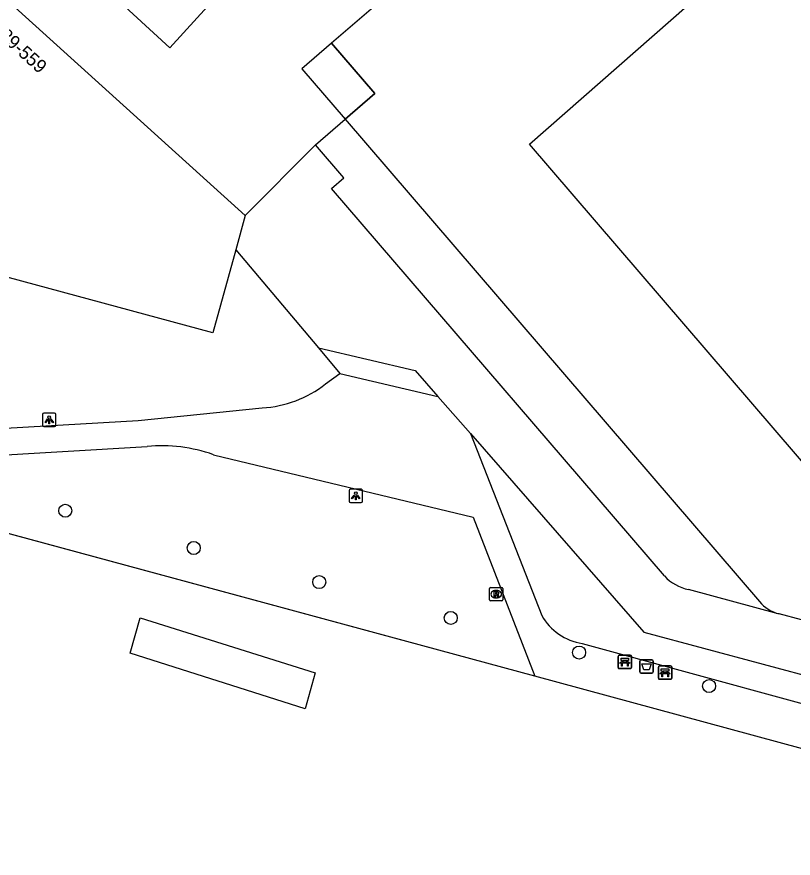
# Model space of a CAD drawing. Extents: x 161772 to 163123, y 383092 to 383917.
# Drawn here: x 162073.6 to 162131.9, y 383101.7 to 383164.9 of the extents above; entities that cross this region are included whole.
import ezdxf

# ---------------------------------------------------------------- set-up
doc = ezdxf.new("R2010")
doc.units = 0
for name, color, linetype in [('IMGEO_Afvalbak', 7, 'Continuous'), ('IMGEO_Bank', 7, 'Continuous'), ('IMGEO_Boom', 7, 'Continuous'), ('IMGEO_Kademuur', 7, 'Continuous'), ('IMGEO_Lichtpunt', 7, 'Continuous'), ('IMGEO_Pand', 7, 'Continuous'), ('IMGEO_Pand_nummerreeks', 7, 'Continuous'), ('IMGEO_Pand_overbouw', 7, 'Continuous'), ('IMGEO_Rioolput', 7, 'Continuous'), ('IMGEO_Voetpad_halfverhard', 7, 'Continuous'), ('IMGEO_Voetpad_op_trap', 7, 'Continuous'), ('IMGEO_Voetpad_open', 7, 'Continuous'), ('IMGEO_Waterloop', 7, 'Continuous')]:
    doc.layers.add(name, color=color, linetype=linetype)

msp = doc.modelspace()

# ---------------------------------------------------------------- linework, layer by layer
at = {"layer": 'IMGEO_Afvalbak'}
for p, q in [((162120.378, 383115.683), (162120.378, 383116.483)), ((162120.378, 383116.483), (162120.378, 383115.683)), ((162120.478, 383116.583), (162121.268, 383116.583)), ((162121.268, 383116.583), (162120.478, 383116.583)), ((162121.368, 383116.483), (162121.368, 383115.683)), ((162121.368, 383115.683), (162121.368, 383116.483)), ((162121.268, 383115.583), (162120.478, 383115.583)), ((162120.478, 383115.583), (162121.268, 383115.583))]:
    msp.add_line(p, q, dxfattribs=at)
msp.add_lwpolyline([(162120.521, 383116.297), (162121.225, 383116.297), (162121.076, 383115.827), (162120.67, 383115.827), (162120.521, 383116.297)], dxfattribs=at)
for centre, start, end in [((162120.478, 383116.483), 90, 180), ((162120.478, 383116.483), 90, 180), ((162121.268, 383116.483), 0, 90), ((162121.268, 383116.483), 360, 90), ((162120.478, 383115.683), 180, 270), ((162120.478, 383115.683), 180, 270), ((162121.268, 383115.683), 270, 0), ((162121.268, 383115.683), 270, 0)]:
    msp.add_arc(centre, 0.1, start, end, dxfattribs=at)
at = {"layer": 'IMGEO_Bank'}
for p, q in [((162118.744, 383116.003), (162118.744, 383116.844)), ((162118.744, 383116.844), (162118.744, 383116.003)), ((162118.819, 383116.928), (162119.66, 383116.928)), ((162119.66, 383116.928), (162118.819, 383116.928)), ((162119.053, 383116.434), (162119.053, 383116.54)), ((162119.097, 383116.54), (162119.097, 383116.434)), ((162119.385, 383116.546), (162119.103, 383116.546)), ((162119.103, 383116.428), (162119.385, 383116.428)), ((162119.391, 383116.434), (162119.391, 383116.54)), ((162119.435, 383116.54), (162119.435, 383116.434)), ((162119.744, 383116.853), (162119.744, 383116.012)), ((162119.744, 383116.012), (162119.744, 383116.853)), ((162119.669, 383115.928), (162118.828, 383115.928)), ((162118.828, 383115.928), (162119.669, 383115.928)), ((162119.441, 383116.326), (162119.048, 383116.326)), ((162121.77, 383115.203), (162121.77, 383116.044)), ((162121.77, 383116.044), (162121.77, 383115.203)), ((162121.845, 383116.128), (162122.686, 383116.128)), ((162122.686, 383116.128), (162121.845, 383116.128)), ((162122.77, 383116.053), (162122.77, 383115.212)), ((162122.77, 383115.212), (162122.77, 383116.053)), ((162122.467, 383115.526), (162122.074, 383115.526)), ((162122.079, 383115.634), (162122.079, 383115.74)), ((162122.123, 383115.74), (162122.123, 383115.634)), ((162122.411, 383115.746), (162122.129, 383115.746)), ((162122.129, 383115.628), (162122.411, 383115.628)), ((162122.417, 383115.634), (162122.417, 383115.74)), ((162122.461, 383115.74), (162122.461, 383115.634)), ((162122.695, 383115.128), (162121.854, 383115.128)), ((162121.854, 383115.128), (162122.695, 383115.128))]:
    msp.add_line(p, q, dxfattribs=at)
for points in [[(162118.991, 383116.326), (162118.849, 383116.326), (162118.961, 383116.428), (162119.047, 383116.428)], [(162119.047, 383116.546), (162118.961, 383116.546), (162118.961, 383116.707), (162119.524, 383116.707), (162119.524, 383116.546), (162119.441, 383116.546)], [(162119.441, 383116.428), (162119.524, 383116.428), (162119.636, 383116.326), (162119.497, 383116.326)], [(162119.041, 383116.319), (162119.041, 383116.112), (162118.998, 383116.112), (162118.998, 383116.319)], [(162119.491, 383116.319), (162119.491, 383116.112), (162119.447, 383116.112), (162119.447, 383116.319)], [(162122.073, 383115.746), (162121.987, 383115.746), (162121.987, 383115.907), (162122.55, 383115.907), (162122.55, 383115.746), (162122.467, 383115.746)], [(162122.017, 383115.526), (162121.875, 383115.526), (162121.987, 383115.628), (162122.073, 383115.628)], [(162122.067, 383115.519), (162122.067, 383115.312), (162122.024, 383115.312), (162122.024, 383115.519)], [(162122.467, 383115.628), (162122.55, 383115.628), (162122.662, 383115.526), (162122.523, 383115.526)], [(162122.517, 383115.519), (162122.517, 383115.312), (162122.473, 383115.312), (162122.473, 383115.519)]]:
    msp.add_lwpolyline(points, dxfattribs=at)
for centre, radius, start, end in [((162118.822, 383116.85), 0.0779, 92.4484, 184.28452), ((162118.822, 383116.85), 0.0779, 92.4484, 184.28452), ((162119.046, 383116.539), 0.00671, 2.89567, 87.10433), ((162119.046, 383116.435), 0.00671, 272.89567, 357.10433), ((162119.103, 383116.539), 0.00671, 92.89567, 177.10433), ((162119.103, 383116.435), 0.00671, 182.89567, 267.10433), ((162119.385, 383116.539), 0.00671, 2.89567, 87.10433), ((162119.385, 383116.435), 0.00671, 272.89567, 357.10433), ((162119.442, 383116.539), 0.00671, 92.89567, 177.10433), ((162119.442, 383116.435), 0.00671, 182.89567, 267.10433), ((162119.666, 383116.85), 0.0779, 2.4484, 94.28452), ((162119.666, 383116.85), 0.0779, 2.4484, 94.28452), ((162118.822, 383116.006), 0.0779, 182.4484, 274.28452), ((162118.822, 383116.006), 0.0779, 182.4484, 274.28452), ((162118.991, 383116.319), 0.00671, 2.89567, 87.10433), ((162119.048, 383116.319), 0.00671, 92.89567, 177.10433), ((162119.44, 383116.319), 0.00671, 2.89567, 87.10433), ((162119.497, 383116.319), 0.00671, 92.89567, 177.10433), ((162119.666, 383116.006), 0.0779, 272.4484, 4.28452), ((162119.666, 383116.006), 0.0779, 272.4484, 4.28452), ((162121.848, 383116.05), 0.0779, 92.4484, 184.28452), ((162121.848, 383116.05), 0.0779, 92.4484, 184.28452), ((162122.692, 383116.05), 0.0779, 2.4484, 94.28452), ((162122.692, 383116.05), 0.0779, 2.4484, 94.28452), ((162121.848, 383115.206), 0.0779, 182.4484, 274.28452), ((162121.848, 383115.206), 0.0779, 182.4484, 274.28452), ((162122.017, 383115.519), 0.00671, 2.89567, 87.10433), ((162122.074, 383115.519), 0.00671, 92.89567, 177.10433), ((162122.072, 383115.739), 0.00671, 2.89567, 87.10433), ((162122.072, 383115.635), 0.00671, 272.89567, 357.10433), ((162122.129, 383115.739), 0.00671, 92.89567, 177.10433), ((162122.129, 383115.635), 0.00671, 182.89567, 267.10433), ((162122.411, 383115.739), 0.00671, 2.89567, 87.10433), ((162122.411, 383115.635), 0.00671, 272.89567, 357.10433), ((162122.468, 383115.739), 0.00671, 92.89567, 177.10433), ((162122.468, 383115.635), 0.00671, 182.89567, 267.10433), ((162122.466, 383115.519), 0.00671, 2.89567, 87.10433), ((162122.523, 383115.519), 0.00671, 92.89567, 177.10433), ((162122.692, 383115.206), 0.0779, 272.4484, 4.28452), ((162122.692, 383115.206), 0.0779, 272.4484, 4.28452)]:
    msp.add_arc(centre, radius, start, end, dxfattribs=at)
at = {"layer": 'IMGEO_Boom'}
for centre in [(162077.237, 383127.78), (162086.879, 383124.982), (162096.299, 383122.42), (162106.18, 383119.729), (162115.812, 383117.136), (162125.576, 383114.619)]:
    msp.add_circle(centre, 0.489, dxfattribs=at)
at = {"layer": 'IMGEO_Kademuur'}
msp.add_lwpolyline([(162139.881, 383107.934), (162112.481, 383115.352), (162000, 383145.804), (161986.972, 383149.331), (161990.33, 383163.776)], dxfattribs=at)
at = {"layer": 'IMGEO_Lichtpunt'}
for p, q in [((162075.527, 383135.012), (162075.527, 383134.205)), ((162075.527, 383135.012), (162075.527, 383134.205)), ((162076.429, 383135.107), (162075.621, 383135.107)), ((162076.429, 383135.107), (162075.621, 383135.107)), ((162076.523, 383134.205), (162076.523, 383135.012)), ((162076.523, 383134.205), (162076.523, 383135.012)), ((162075.621, 383134.111), (162076.429, 383134.111)), ((162075.621, 383134.111), (162076.429, 383134.111)), ((162098.546, 383129.293), (162098.546, 383128.486)), ((162098.546, 383129.293), (162098.546, 383128.486)), ((162099.448, 383129.388), (162098.64, 383129.388)), ((162099.448, 383129.388), (162098.64, 383129.388)), ((162099.542, 383128.486), (162099.542, 383129.293)), ((162099.542, 383128.486), (162099.542, 383129.293)), ((162098.64, 383128.392), (162099.448, 383128.392)), ((162098.64, 383128.392), (162099.448, 383128.392))]:
    msp.add_line(p, q, dxfattribs=at)
for points in [[(162075.901, 383134.676), (162075.94, 383134.648), (162075.752, 383134.386), (162075.714, 383134.413), (162075.901, 383134.676)], [(162076.003, 383134.628), (162076.05, 383134.628), (162076.05, 383134.306), (162076.003, 383134.306), (162076.003, 383134.628)], [(162076.113, 383134.648), (162076.151, 383134.675), (162076.338, 383134.413), (162076.299, 383134.385), (162076.113, 383134.648)], [(162098.92, 383128.957), (162098.959, 383128.929), (162098.771, 383128.667), (162098.733, 383128.694), (162098.92, 383128.957)], [(162099.022, 383128.909), (162099.069, 383128.909), (162099.069, 383128.587), (162099.022, 383128.587), (162099.022, 383128.909)], [(162099.132, 383128.929), (162099.17, 383128.956), (162099.357, 383128.694), (162099.318, 383128.666), (162099.132, 383128.929)]]:
    msp.add_lwpolyline(points, dxfattribs=at)
for centre in [(162076.026, 383134.81), (162099.045, 383129.091)]:
    msp.add_circle(centre, 0.0994, dxfattribs=at)
for centre, start, end in [((162075.621, 383135.012), 90, 180), ((162075.621, 383135.012), 90, 180), ((162076.429, 383135.012), 0, 90), ((162076.429, 383135.012), 0, 90), ((162075.621, 383134.205), 180, 270), ((162075.621, 383134.205), 180, 270), ((162076.429, 383134.205), 270, 0), ((162076.429, 383134.205), 270, 360), ((162098.64, 383129.293), 90, 180), ((162098.64, 383129.293), 90, 180), ((162099.448, 383129.293), 0, 90), ((162099.448, 383129.293), 0, 90), ((162098.64, 383128.486), 180, 270), ((162098.64, 383128.486), 180, 270), ((162099.448, 383128.486), 270, 0), ((162099.448, 383128.486), 270, 360)]:
    msp.add_arc(centre, 0.0946, start, end, dxfattribs=at)
at = {"layer": 'IMGEO_Pand'}
for points in [[(162139.223, 383117.778), (162140.452, 383122.295), (162112.091, 383155.294), (162125.343, 383166.944), (162129.136, 383170.203), (162178.188, 383212.413), (162208.444, 383177.204)], [(162065.834, 383172.455), (162090.748, 383149.931)], [(162107.386, 383171.613), (162097.231, 383162.88), (162100.485, 383159.097), (162098.244, 383157.17)], [(162098.244, 383157.17), (162129.36, 383120.964)], [(162090.04, 383147.373), (162088.311, 383141.123), (162051.363, 383151.118), (162045.642, 383156.284)], [(162090.748, 383149.931), (162090.04, 383147.373)], [(162139.223, 383117.778), (162130.824, 383120.032)]]:
    msp.add_lwpolyline(points, dxfattribs=at)
msp.add_arc((162131.618, 383122.895), 2.971, 220.5365, 254.50086, dxfattribs=at)
at = {"layer": 'IMGEO_Pand_overbouw'}
msp.add_lwpolyline([(162094.991, 383160.954), (162098.244, 383157.17), (162100.485, 383159.097), (162097.231, 383162.88)], close=True, dxfattribs=at)
at = {"layer": 'IMGEO_Rioolput'}
for p, q in [((162109.087, 383121.088), (162109.087, 383121.94)), ((162109.162, 383122.014), (162110.014, 383122.014)), ((162109.575, 383121.794), (162109.6, 383121.794)), ((162110.088, 383121.94), (162110.088, 383121.088)), ((162110.014, 383121.014), (162109.162, 383121.014)), ((162109.598, 383121.234), (162109.573, 383121.234))]:
    msp.add_line(p, q, dxfattribs=at)
for points in [[(162109.087, 383121.088), (162109.087, 383121.94)], [(162109.162, 383122.014), (162110.014, 383122.014)], [(162109.676, 383121.712), (162109.424, 383121.714), (162109.424, 383121.314)], [(162109.424, 383121.314), (162109.548, 383121.314), (162109.548, 383121.476), (162109.559, 383121.476)], [(162109.602, 383121.633), (162109.548, 383121.633), (162109.548, 383121.552)], [(162109.548, 383121.552), (162109.6, 383121.552)], [(162110.088, 383121.94), (162110.088, 383121.088)], [(162110.014, 383121.014), (162109.162, 383121.014)], [(162109.606, 383121.447), (162109.677, 383121.314), (162109.817, 383121.314), (162109.752, 383121.44)]]:
    msp.add_lwpolyline(points, dxfattribs=at)
for centre, radius, start, end in [((162109.164, 383121.938), 0.0765, 91.55205, 178.44795), ((162109.164, 383121.938), 0.0765, 91.55205, 178.44795), ((162109.558, 383121.423), 0.0533, 26.02933, 88.69889), ((162109.584, 383121.741), 0.19, 274.7715, 282.96867), ((162109.608, 383121.537), 0.0964, 77.00612, 93.18647), ((162109.622, 383121.594), 0.0378, 276.66336, 79.67722), ((162109.675, 383121.602), 0.109, 350.36119, 89.41601), ((162109.673, 383121.602), 0.112, 277.58423, 350.98172), ((162109.657, 383121.387), 0.108, 29.51342, 73.79051), ((162110.012, 383121.938), 0.0765, 1.55205, 88.44795), ((162110.012, 383121.938), 0.0765, 1.55205, 88.44795), ((162109.164, 383121.09), 0.0765, 181.55205, 268.44795), ((162109.164, 383121.09), 0.0765, 181.55205, 268.44795), ((162110.012, 383121.09), 0.0765, 271.55205, 358.44795), ((162110.012, 383121.09), 0.0765, 271.55205, 358.44795)]:
    msp.add_arc(centre, radius, start, end, dxfattribs=at)
for centre, major_axis, ratio, start_param, end_param in [((162109.574, 383121.514), (-0.387, 0.002), 0.722429, 4.712389, 7.853982), ((162109.599, 383121.514), (-0.39, 0.002), 0.717154, 1.570796, 4.712389)]:
    msp.add_ellipse(centre, major_axis=major_axis, ratio=ratio, start_param=start_param, end_param=end_param, dxfattribs=at)
at = {"layer": 'IMGEO_Voetpad_halfverhard'}
for points in [[(162096.776, 383137.296), (162097.855, 383138.08)], [(162097.855, 383138.08), (162105.199, 383136.357)], [(162071.411, 383133.9), (162082.709, 383134.559), (162092.017, 383135.492)], [(162107.651, 383133.565), (162113.004, 383119.905)], [(162070.646, 383131.858), (162083.389, 383132.602)], [(162088.354, 383131.986), (162107.854, 383127.294), (162112.481, 383115.352)], [(162116.054, 383117.82), (162164.452, 383104.613)], [(162162.911, 383101.699), (162139.881, 383107.934), (162112.481, 383115.352)]]:
    msp.add_lwpolyline(points, dxfattribs=at)
for centre, radius, start, end in [((162091.494, 383144.052), 8.576, 273.49832, 308.02223), ((162084.492, 383121.177), 11.478, 70.33904, 95.51604), ((162116.722, 383122.07), 4.302, 210.21459, 261.07187)]:
    msp.add_arc(centre, radius, start, end, dxfattribs=at)
at = {"layer": 'IMGEO_Voetpad_op_trap'}
msp.add_lwpolyline([(162096.241, 383139.999), (162097.855, 383138.08)], dxfattribs=at)
at = {"layer": 'IMGEO_Voetpad_open'}
for points in [[(162098.438, 383179.252), (162099.474, 383178.349), (162085.086, 383162.538), (162080.797, 383166.469)], [(162096.013, 383155.252), (162098.244, 383157.17)], [(162096.013, 383155.252), (162090.748, 383149.931)], [(162122.226, 383122.889), (162114.709, 383131.622), (162106.585, 383141.088), (162097.219, 383151.963), (162098.152, 383152.768), (162096.013, 383155.252)], [(162090.04, 383147.373), (162096.241, 383139.999)], [(162096.241, 383139.999), (162103.495, 383138.298), (162105.199, 383136.357)], [(162105.199, 383136.357), (162107.651, 383133.565)], [(162107.651, 383133.565), (162120.663, 383118.667), (162165.483, 383106.648)], [(162130.824, 383120.032), (162130.761, 383120.044), (162124.032, 383121.861)]]:
    msp.add_lwpolyline(points, dxfattribs=at)
msp.add_arc((162124.699, 383125.133), 3.34, 222.22475, 258.477, dxfattribs=at)
at = {"layer": 'IMGEO_Waterloop'}
for points in [[(162112.481, 383115.352), (162029.115, 383137.922)], [(162095.258, 383112.916), (162082.102, 383117.077), (162082.852, 383119.729), (162096.007, 383115.615), (162095.258, 383112.916)]]:
    msp.add_lwpolyline(points, dxfattribs=at)

# ---------------------------------------------------------------- texts
at = {"layer": 'IMGEO_Pand_nummerreeks'}
msp.add_text('489-559', height=1, rotation=317.88187, dxfattribs=at).set_placement((162071.645, 383163.832))

doc.saveas('drawing.dxf')
